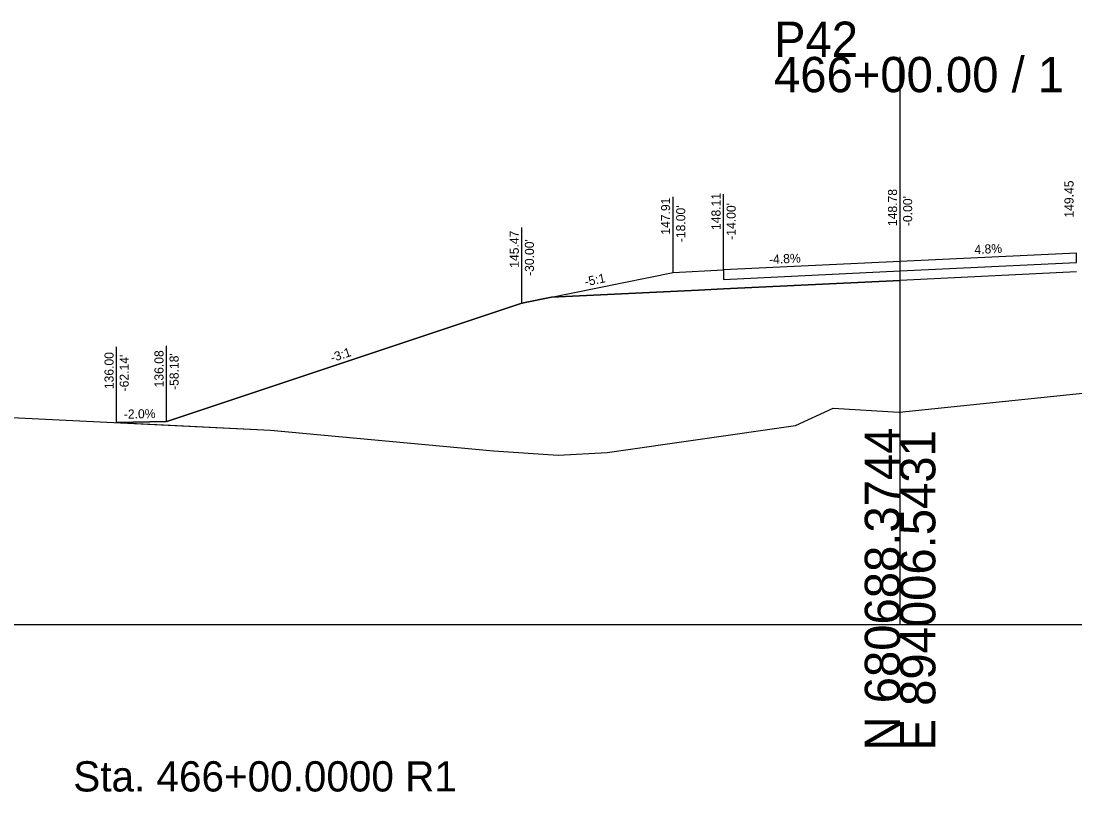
# Model space of a CAD drawing. Extents: x -26 to 4403, y -13 to 9578.
# Drawn here: x 1180.3 to 1263.9, y 7486.7 to 7547.8 of the extents above; entities that cross this region are included whole.
import ezdxf

# ---------------------------------------------------------------- set-up
doc = ezdxf.new("R2010")
doc.units = 0
for name, color, linetype in [('_CIVIL_CONSTRUCTION', 7, 'Continuous'), ('CONST_DCH', 7, 'Continuous'), ('CONST_LV3', 7, 'Continuous'), ('Draft_XS_Text', 7, 'Continuous'), ('DTM_CORRIDOR', 7, 'Continuous'), ('DTM_TEMP_DROP', 7, 'Continuous'), ('DTM_X_GROUND', 7, 'Continuous'), ('SLOPE_STAKES_FILL', 7, 'Continuous'), ('XS_CELL', 7, 'Continuous'), ('XS_M_SHAPES_EARTHWORK', 7, 'Continuous'), ('XS_P_ASPHALT', 7, 'Continuous'), ('XS_P_GROUND', 7, 'Continuous'), ('XS_P_SHOULDER', 7, 'Continuous'), ('XS_P_SUBGRADE_GRANULAR', 7, 'Continuous'), ('XS_P_TX_CLEARZONE', 7, 'Continuous'), ('XS_P_TX_FS_BS', 7, 'Continuous')]:
    doc.layers.add(name, color=color, linetype=linetype)

msp = doc.modelspace()

# ---------------------------------------------------------------- linework, layer by layer
at = {"layer": 'CONST_LV3'}
msp.add_lwpolyline([(1220, 7525.473), (1220, 7525.473), (1222.35, 7525.951)], dxfattribs=at)
at = {"layer": 'DTM_X_GROUND'}
msp.add_lwpolyline([(1159.518, 7517.394), (1200.052, 7515.401), (1217.74, 7513.76), (1222.892, 7513.417), (1226.763, 7513.627), (1241.699, 7515.779), (1244.696, 7517.139), (1249.906, 7516.828), (1249.956, 7516.833), (1276.709, 7519.611), (1283.124, 7519.79), (1294.202, 7520.766), (1295.632, 7520.835), (1310.279, 7520.767), (1331.863, 7520.749), (1369.14, 7520.527), (1389.173, 7520.495), (1400, 7520.407)], dxfattribs=at)
at = {"layer": 'XS_CELL'}
for p, q in [((1250, 7500), (1250, 7545)), ((1000, 7500), (1250, 7500)), ((1250, 7500), (1400, 7500))]:
    msp.add_line(p, q, dxfattribs=at)
at = {"layer": 'XS_M_SHAPES_EARTHWORK'}
msp.add_lwpolyline([(1264, 7527.95), (1250, 7527.278), (1236, 7526.606), (1234, 7526.51), (1222.35, 7525.951), (1220, 7525.473), (1194.538, 7516.986), (1192.069, 7516.163), (1191.818, 7516.08), (1187.859, 7516.001), (1200.052, 7515.401), (1217.74, 7513.76), (1222.892, 7513.417), (1226.763, 7513.627), (1241.699, 7515.779), (1244.696, 7517.139), (1249.906, 7516.828), (1249.956, 7516.833), (1276.709, 7519.611)], dxfattribs=at)
at = {"layer": 'XS_P_ASPHALT'}
msp.add_lwpolyline([(1250, 7528.778), (1236, 7528.106), (1236, 7528.106), (1236, 7527.356), (1250, 7528.028), (1250, 7528.028), (1264, 7528.7), (1264, 7528.7), (1264, 7529.45), (1264, 7529.45), (1264, 7529.45), (1250, 7528.778), (1250, 7528.778)], dxfattribs=at)
at = {"layer": 'XS_P_GROUND'}
for points in [[(1191.818, 7516.08), (1192.069, 7516.163), (1192.069, 7516.163), (1194.538, 7516.986), (1194.538, 7516.986), (1220, 7525.473), (1232, 7527.914), (1232, 7527.914)], [(1187.859, 7516.001), (1191.818, 7516.08)]]:
    msp.add_lwpolyline(points, dxfattribs=at)
at = {"layer": 'XS_P_SHOULDER'}
msp.add_lwpolyline([(1232, 7527.914), (1236, 7528.106), (1236, 7528.106)], dxfattribs=at)
at = {"layer": 'XS_P_SUBGRADE_GRANULAR'}
for points in [[(1264, 7527.95), (1264, 7527.95), (1250, 7527.278)], [(1236, 7526.606), (1250, 7527.278), (1250, 7527.278)], [(1222.35, 7525.951), (1222.35, 7525.951), (1234, 7526.51), (1236, 7526.606), (1236, 7526.606)]]:
    msp.add_lwpolyline(points, dxfattribs=at)
at = {"layer": 'XS_P_TX_CLEARZONE'}
for p, q in [((1250, 7528.778), (1250, 7534.778)), ((1250, 7528.778), (1250, 7534.778)), ((1250, 7528.778), (1250, 7534.778)), ((1250, 7528.778), (1250, 7534.778)), ((1250, 7528.778), (1250, 7534.778)), ((1250, 7528.778), (1250, 7534.778)), ((1232, 7527.914), (1232, 7533.914)), ((1232, 7527.914), (1232, 7533.914)), ((1232, 7527.914), (1232, 7533.914)), ((1236, 7528.106), (1236, 7534.106)), ((1236, 7528.106), (1236, 7534.106)), ((1236, 7528.106), (1236, 7534.106)), ((1236, 7528.106), (1236, 7534.106)), ((1236, 7528.106), (1236, 7534.106)), ((1236, 7528.106), (1236, 7534.106)), ((1220, 7525.473), (1220, 7531.473)), ((1220, 7525.473), (1220, 7531.473)), ((1220, 7525.473), (1220, 7531.473)), ((1187.859, 7516.001), (1187.859, 7522.001)), ((1187.859, 7516.001), (1187.859, 7522.001)), ((1187.859, 7516.001), (1187.859, 7522.001)), ((1187.859, 7516.001), (1187.859, 7522.001)), ((1187.859, 7516.001), (1187.859, 7522.001)), ((1187.859, 7516.001), (1187.859, 7522.001)), ((1191.818, 7516.08), (1191.818, 7522.08)), ((1191.818, 7516.08), (1191.818, 7522.08)), ((1191.818, 7516.08), (1191.818, 7522.08))]:
    msp.add_line(p, q, dxfattribs=at)

# ---------------------------------------------------------------- texts
at = {"layer": '_CIVIL_CONSTRUCTION'}
for p in [(1249.961, 7528.718), (1235.961, 7528.046)]:
    msp.add_text('X', height=0.12, dxfattribs=at).set_placement(p)
at = {"layer": 'CONST_DCH'}
msp.add_text('X', height=0.12, dxfattribs=at).set_placement((1191.779, 7516.02))
at = {"layer": 'Draft_XS_Text'}
msp.add_text('Sta. 466+00.0000 R1', height=2.4, dxfattribs=at).set_placement((1184.42, 7486.75))
at = {"layer": 'DTM_CORRIDOR'}
msp.add_text('X', height=0.12, dxfattribs=at).set_placement((1187.82, 7515.941))
at = {"layer": 'DTM_TEMP_DROP'}
msp.add_text('X', height=0.12, dxfattribs=at).set_placement((1231.961, 7527.854))
at = {"layer": 'SLOPE_STAKES_FILL'}
msp.add_text('X', height=0.12, dxfattribs=at).set_placement((1219.961, 7525.413))
at = {"layer": 'XS_CELL'}
for s, p in [('P42', (1240, 7545)), ('466+00.00 / 1', (1240, 7542.2))]:
    msp.add_text(s, height=2.8, dxfattribs=at).set_placement(p)
for s, p in [('N 680688.3744', (1250, 7490)), ('E 894006.5431', (1252.8, 7490))]:
    msp.add_text(s, height=2.8, rotation=90, dxfattribs=at).set_placement(p)
at = {"layer": 'XS_P_TX_CLEARZONE'}
for s, p in [('149.45', (1263.76, 7532.255)), ('149.45', (1263.76, 7532.255)), ('149.45', (1263.76, 7532.255)), ('149.45', (1263.76, 7532.255)), ('149.45', (1263.76, 7532.255)), ('149.45', (1263.76, 7532.255)), ('147.91', (1231.76, 7530.9)), ('147.91', (1231.76, 7530.9)), ('147.91', (1231.76, 7530.9)), ('148.11', (1235.76, 7531.273)), ('148.11', (1235.76, 7531.273)), ('148.11', (1235.76, 7531.273)), ('148.11', (1235.76, 7531.273)), ('148.11', (1235.76, 7531.273)), ('148.11', (1235.76, 7531.273)), ('148.78', (1249.76, 7531.583)), ('148.78', (1249.76, 7531.583)), ('148.78', (1249.76, 7531.583)), ('148.78', (1249.76, 7531.583)), ('148.78', (1249.76, 7531.583)), ('148.78', (1249.76, 7531.583)), ("-0.00'", (1250.96, 7531.583)), ("-0.00'", (1250.96, 7531.583)), ("-0.00'", (1250.96, 7531.583)), ("-0.00'", (1250.96, 7531.583)), ("-0.00'", (1250.96, 7531.583)), ("-0.00'", (1250.96, 7531.583)), ("-18.00'", (1232.96, 7530.31)), ("-18.00'", (1232.96, 7530.31)), ("-18.00'", (1232.96, 7530.31)), ("-14.00'", (1236.96, 7530.502)), ("-14.00'", (1236.96, 7530.502)), ("-14.00'", (1236.96, 7530.502)), ("-14.00'", (1236.96, 7530.502)), ("-14.00'", (1236.96, 7530.502)), ("-14.00'", (1236.96, 7530.502)), ('145.47', (1219.76, 7528.277)), ('145.47', (1219.76, 7528.277)), ('145.47', (1219.76, 7528.277)), ("-30.00'", (1220.96, 7527.631)), ("-30.00'", (1220.96, 7527.631)), ("-30.00'", (1220.96, 7527.631)), ('136.00', (1187.619, 7518.652)), ('136.00', (1187.619, 7518.652)), ('136.00', (1187.619, 7518.652)), ('136.00', (1187.619, 7518.652)), ('136.00', (1187.619, 7518.652)), ('136.00', (1187.619, 7518.652)), ("-62.14'", (1188.819, 7518.476)), ("-62.14'", (1188.819, 7518.476)), ("-62.14'", (1188.819, 7518.476)), ("-62.14'", (1188.819, 7518.476)), ("-62.14'", (1188.819, 7518.476)), ("-62.14'", (1188.819, 7518.476)), ('136.08', (1191.578, 7518.794)), ('136.08', (1191.578, 7518.794)), ('136.08', (1191.578, 7518.794)), ("-58.18'", (1192.778, 7518.589)), ("-58.18'", (1192.778, 7518.589)), ("-58.18'", (1192.778, 7518.589))]:
    msp.add_text(s, height=0.72, rotation=90, dxfattribs=at).set_placement(p)
at = {"layer": 'XS_P_TX_FS_BS'}
for s, rotation, p in [('4.8%', 2.74809, (1255.913, 7529.363)), ('4.8%', 2.74809, (1255.913, 7529.363)), ('4.8%', 2.74809, (1255.913, 7529.363)), ('-4.8%', 2.74809, (1239.619, 7528.58)), ('-4.8%', 2.74809, (1239.619, 7528.58)), ('-4.8%', 2.74809, (1239.619, 7528.58)), ('-5:1', 11.49969, (1225.051, 7526.807)), ('-5:1', 11.49969, (1225.051, 7526.807)), ('-5:1', 11.49969, (1225.051, 7526.807)), ('-3:1', 18.43323, (1204.954, 7520.774)), ('-3:1', 18.43323, (1204.954, 7520.774)), ('-3:1', 18.43323, (1204.954, 7520.774)), ('-2.0%', 1.14576, (1188.436, 7516.312)), ('-2.0%', 1.14576, (1188.436, 7516.312)), ('-2.0%', 1.14576, (1188.436, 7516.312))]:
    msp.add_text(s, height=0.72, rotation=rotation, dxfattribs=at).set_placement(p)

doc.saveas('drawing.dxf')
